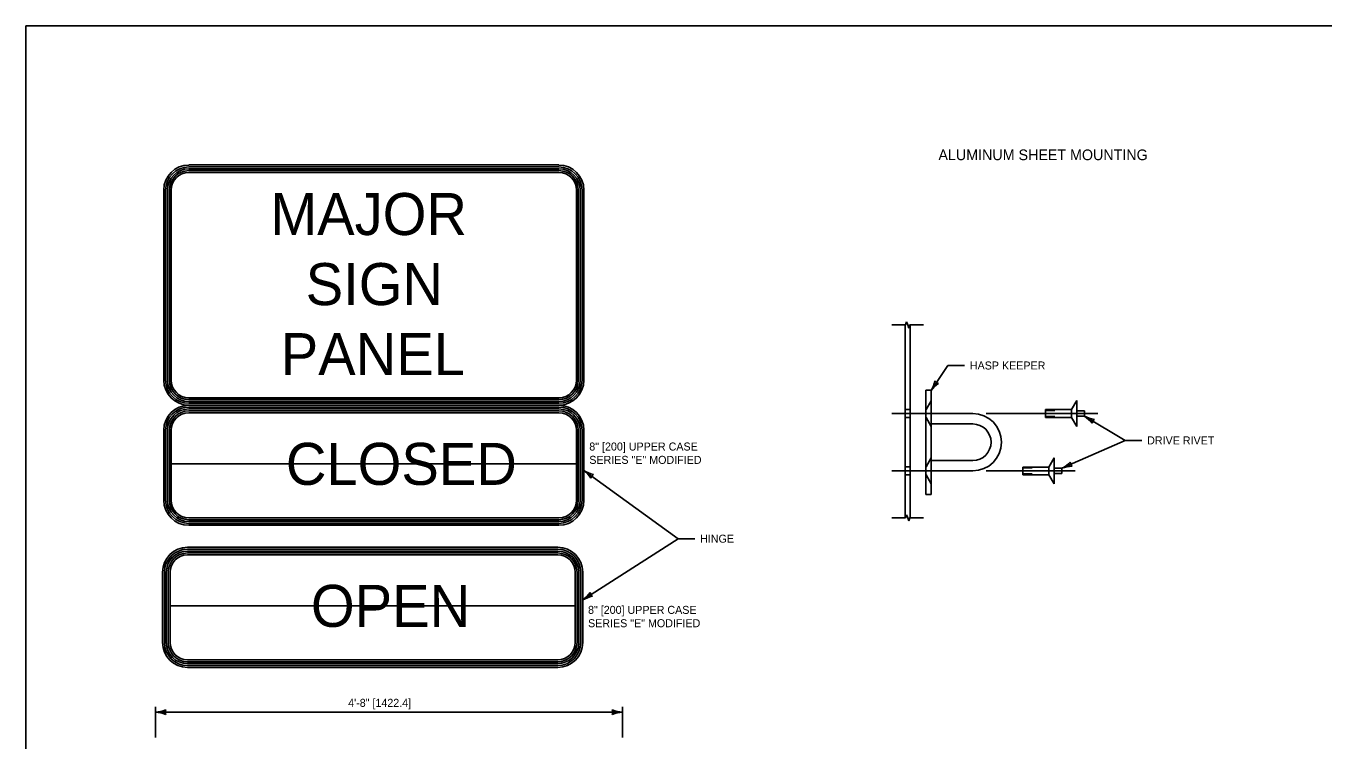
# Model space of a CAD drawing. Extents: x 49991.4 to 50021, y 49987.6 to 50011.4.
# Drawn here: x 49999.38 to 50009.11, y 49993.65 to 49999 of the extents above; entities that cross this region are included whole.
import ezdxf

# ---------------------------------------------------------------- set-up
doc = ezdxf.new("R2010")
doc.units = 0
for name, color, linetype in [('Level 1', 7, 'Continuous'), ('Level 2', 7, 'Continuous'), ('Level 3', 7, 'Continuous'), ('Level 4', 7, 'Continuous'), ('Level 5', 7, 'Continuous'), ('Level 6', 7, 'Continuous')]:
    doc.layers.add(name, color=color, linetype=linetype)

msp = doc.modelspace()

# ---------------------------------------------------------------- linework, layer by layer
at = {"layer": 'Level 1'}
for p, q in [((50003.3795, 49997.9572), (50000.6042, 49997.9572)), ((50003.3795, 49997.9431), (50000.6042, 49997.9431)), ((50003.3795, 49997.9291), (50000.6042, 49997.9291)), ((50003.3795, 49997.915), (50000.6042, 49997.915)), ((50003.3795, 49997.901), (50000.6042, 49997.901)), ((50000.4167, 49997.7697), (50000.4167, 49996.3447)), ((50000.4307, 49997.7697), (50000.4307, 49996.3447)), ((50000.4448, 49997.7697), (50000.4448, 49996.3447)), ((50000.4588, 49997.7697), (50000.4588, 49996.3447)), ((50000.4729, 49997.7697), (50000.4729, 49996.3447)), ((50003.5107, 49996.3447), (50003.5107, 49997.7697)), ((50003.5247, 49996.3447), (50003.5247, 49997.7697)), ((50003.5388, 49996.3447), (50003.5388, 49997.7697)), ((50003.5528, 49996.3447), (50003.5528, 49997.7697)), ((50003.567, 49996.3447), (50003.567, 49997.7697)), ((50005.9746, 49996.7584), (50005.9746, 49995.3132)), ((50006.0136, 49996.7584), (50006.0136, 49995.3132)), ((50000.6042, 49996.2135), (50003.3795, 49996.2135)), ((50000.6042, 49996.1993), (50003.3795, 49996.1993)), ((50000.6042, 49996.1853), (50003.3795, 49996.1853)), ((50006.1308, 49996.2703), (50006.1308, 49995.4891)), ((50006.1308, 49996.2703), (50006.1698, 49996.2703)), ((50006.1698, 49996.2703), (50006.1698, 49995.4891)), ((50007.2612, 49996.1919), (50007.2222, 49996.1237)), ((50007.2612, 49996.1919), (50007.2612, 49995.9967)), ((50000.6042, 49996.1712), (50003.3795, 49996.1712)), ((50000.6042, 49996.1572), (50003.3795, 49996.1572)), ((50003.3795, 49996.1431), (50000.6042, 49996.1431)), ((50003.3795, 49996.1291), (50000.6042, 49996.1291)), ((50003.3795, 49996.115), (50000.6042, 49996.115)), ((50003.3795, 49996.1009), (50000.6042, 49996.1009)), ((50006.1698, 49996.0944), (50006.4823, 49996.0944)), ((50007.0268, 49996.1237), (50007.2222, 49996.1237)), ((50007.0268, 49996.1237), (50007.0268, 49996.065)), ((50007.0268, 49996.117), (50007.0965, 49996.117)), ((50007.2222, 49996.1237), (50007.2222, 49996.065)), ((50007.2612, 49996.1139), (50007.3198, 49996.1139)), ((50007.3198, 49996.1139), (50007.3198, 49996.0748)), ((50006.1698, 49996.0163), (50006.4823, 49996.0163)), ((50007.0268, 49996.0732), (50007.0965, 49996.0732)), ((50007.0268, 49996.065), (50007.2222, 49996.065)), ((50007.2612, 49995.9967), (50007.2222, 49996.065)), ((50007.2612, 49996.0748), (50007.3198, 49996.0748)), ((50000.4167, 49995.9697), (50000.4167, 49995.4446)), ((50000.4307, 49995.9697), (50000.4307, 49995.4446)), ((50000.4448, 49995.9697), (50000.4448, 49995.4446)), ((50000.4588, 49995.9697), (50000.4588, 49995.4446)), ((50000.4729, 49995.9697), (50000.4729, 49995.4446)), ((50003.5107, 49995.4446), (50003.5107, 49995.9697)), ((50003.5247, 49995.4446), (50003.5247, 49995.9697)), ((50003.5388, 49995.4446), (50003.5388, 49995.9697)), ((50003.5528, 49995.4446), (50003.5528, 49995.9697)), ((50003.567, 49995.4446), (50003.567, 49995.9697)), ((50003.5107, 49995.7174), (50000.4729, 49995.7174)), ((50006.1698, 49995.7428), (50006.4823, 49995.7428)), ((50007.0915, 49995.7623), (50007.0525, 49995.6939)), ((50007.0915, 49995.7623), (50007.0915, 49995.5669)), ((50006.1698, 49995.6646), (50006.4823, 49995.6646)), ((50006.8571, 49995.6939), (50007.0525, 49995.6939)), ((50006.8571, 49995.6939), (50006.8571, 49995.6353)), ((50006.8571, 49995.6874), (50006.9267, 49995.6874)), ((50006.8571, 49995.6434), (50006.9267, 49995.6434)), ((50006.8571, 49995.6353), (50007.0525, 49995.6353)), ((50007.0525, 49995.6939), (50007.0525, 49995.6353)), ((50007.0915, 49995.5669), (50007.0525, 49995.6353)), ((50007.0915, 49995.6841), (50007.15, 49995.6841)), ((50007.0915, 49995.6451), (50007.1501, 49995.6451)), ((50007.15, 49995.6841), (50007.15, 49995.6452)), ((50006.1308, 49995.4891), (50006.1698, 49995.4891)), ((50000.6042, 49995.3132), (50003.3795, 49995.3132)), ((50000.6042, 49995.2991), (50003.3795, 49995.2991)), ((50000.6042, 49995.2851), (50003.3795, 49995.2851)), ((50000.6042, 49995.2709), (50003.3795, 49995.2709)), ((50000.6042, 49995.2569), (50003.3795, 49995.2569)), ((50000.5948, 49995.0921), (50003.3701, 49995.0921)), ((50003.3701, 49995.0781), (50000.5948, 49995.0781)), ((50003.3701, 49995.0639), (50000.5948, 49995.0639)), ((50003.3701, 49995.0499), (50000.5948, 49995.0499)), ((50003.3701, 49995.0358), (50000.5948, 49995.0358)), ((50000.4073, 49994.9046), (50000.4073, 49994.3796)), ((50000.4213, 49994.9046), (50000.4213, 49994.3796)), ((50000.4354, 49994.9046), (50000.4354, 49994.3796)), ((50000.4494, 49994.9046), (50000.4494, 49994.3796)), ((50000.4636, 49994.9046), (50000.4636, 49994.3796)), ((50003.5013, 49994.3796), (50003.5013, 49994.9046)), ((50003.5153, 49994.3796), (50003.5153, 49994.9046)), ((50003.5295, 49994.3796), (50003.5295, 49994.9046)), ((50003.5435, 49994.3796), (50003.5435, 49994.9046)), ((50003.5576, 49994.3796), (50003.5576, 49994.9046)), ((50000.4636, 49994.6532), (50003.5013, 49994.6532)), ((50000.5948, 49994.2483), (50003.3701, 49994.2483)), ((50000.5948, 49994.2343), (50003.3701, 49994.2343)), ((50000.5948, 49994.2202), (50003.3701, 49994.2202)), ((50000.5948, 49994.2062), (50003.3701, 49994.2062)), ((50000.5948, 49994.1921), (50003.3701, 49994.1921))]:
    msp.add_line(p, q, dxfattribs=at)
msp.add_lwpolyline([(49999.3835, 49998.9992), (50016.7501, 49998.9992), (50016.7501, 49987.7988), (49999.3835, 49987.7988)], close=True, dxfattribs=at)
for centre, radius, start, end in [((50000.6043, 49997.7695), 0.1875, 90, 180), ((50000.6043, 49997.7695), 0.1734, 90, 180), ((50003.3793, 49997.7695), 0.1875, 0, 90), ((50003.3793, 49997.7695), 0.1734, 0, 90), ((50000.6043, 49997.7695), 0.1594, 90, 180), ((50000.6043, 49997.7695), 0.1453, 90, 180), ((50000.6043, 49997.7695), 0.1313, 90, 180), ((50003.3793, 49997.7695), 0.1594, 0, 90), ((50003.3793, 49997.7695), 0.1453, 0, 90), ((50003.3793, 49997.7695), 0.1313, 0, 90), ((50000.6043, 49996.3445), 0.1875, 180, 270), ((50000.6043, 49996.3445), 0.1734, 180, 270), ((50000.6043, 49996.3445), 0.1594, 180, 270), ((50000.6043, 49996.3445), 0.1453, 180, 270), ((50000.6043, 49996.3445), 0.1313, 180, 270), ((50003.3793, 49996.3445), 0.1875, 270, 0), ((50003.3793, 49996.3445), 0.1734, 270, 0), ((50003.3793, 49996.3445), 0.1594, 270, 0), ((50003.3793, 49996.3445), 0.1453, 270, 0), ((50003.3793, 49996.3445), 0.1313, 270, 0), ((50000.6043, 49995.9695), 0.1875, 90, 180), ((50000.6043, 49995.9695), 0.1734, 90, 180), ((50000.6043, 49995.9695), 0.1594, 90, 180), ((50000.6043, 49995.9695), 0.1453, 90, 180), ((50000.6043, 49995.9695), 0.1313, 90, 180), ((50003.3793, 49995.9695), 0.1875, 0, 90), ((50003.3793, 49995.9695), 0.1734, 0, 90), ((50003.3793, 49995.9695), 0.1594, 0, 90), ((50003.3793, 49995.9695), 0.1453, 0, 90), ((50003.3793, 49995.9695), 0.1313, 0, 90), ((50006.4823, 49995.8795), 0.2149, 270, 90), ((50006.4823, 49995.8796), 0.1367, 270, 90), ((50000.6043, 49995.4445), 0.1875, 180, 270), ((50000.6043, 49995.4445), 0.1734, 180, 270), ((50000.6043, 49995.4445), 0.1594, 180, 270), ((50000.6043, 49995.4445), 0.1453, 180, 270), ((50000.6043, 49995.4445), 0.1313, 180, 270), ((50003.3793, 49995.4445), 0.1875, 270, 0), ((50003.3793, 49995.4445), 0.1734, 270, 0), ((50003.3793, 49995.4445), 0.1453, 270, 0), ((50003.3793, 49995.4445), 0.1594, 270, 0), ((50003.3793, 49995.4445), 0.1313, 270, 0), ((50000.5949, 49994.9046), 0.1875, 90, 180), ((50000.5949, 49994.9046), 0.1734, 90, 180), ((50000.5949, 49994.9046), 0.1594, 90, 180), ((50000.5949, 49994.9046), 0.1453, 90, 180), ((50000.5949, 49994.9046), 0.1313, 90, 180), ((50003.3699, 49994.9046), 0.1875, 0, 90), ((50003.3699, 49994.9046), 0.1734, 0, 90), ((50003.3699, 49994.9046), 0.1594, 0, 90), ((50003.3699, 49994.9046), 0.1453, 0, 90), ((50003.3699, 49994.9046), 0.1313, 0, 90), ((50000.5949, 49994.3796), 0.1875, 180, 270), ((50000.5949, 49994.3796), 0.1734, 180, 270), ((50000.5949, 49994.3796), 0.1594, 180, 270), ((50000.5949, 49994.3796), 0.1453, 180, 270), ((50000.5949, 49994.3796), 0.1313, 180, 270), ((50003.3699, 49994.3796), 0.1875, 270, 0), ((50003.3699, 49994.3796), 0.1734, 270, 0), ((50003.3699, 49994.3796), 0.1453, 270, 0), ((50003.3699, 49994.3796), 0.1594, 270, 0), ((50003.3699, 49994.3796), 0.1313, 270, 0)]:
    msp.add_arc(centre, radius, start, end, dxfattribs=at)
at = {"layer": 'Level 3'}
for p, q in [((50006.2951, 49996.4547), (50006.1698, 49996.2665)), ((50006.42, 49996.4547), (50006.2951, 49996.4547)), ((50007.3197, 49996.0748), (50007.6244, 49995.8933)), ((50007.6244, 49995.8933), (50007.15, 49995.6841)), ((50007.7493, 49995.8933), (50007.6244, 49995.8933)), ((50004.2728, 49995.1567), (50003.567, 49995.668)), ((50004.2728, 49995.1567), (50003.5576, 49994.6978)), ((50004.3977, 49995.1567), (50004.2728, 49995.1567)), ((50000.3555, 49993.8966), (50000.3555, 49993.6677)), ((50003.8556, 49993.8566), (50000.3555, 49993.8566)), ((50003.8556, 49993.8966), (50003.8556, 49993.6677))]:
    msp.add_line(p, q, dxfattribs=at)
for centre, radius, start, end in [((50005.9697, 49996.3859), 0.233, 329.17497, 348.42482), ((50006.3496, 49996.1358), 0.2223, 123.80367, 143.98718), ((50006.2409, 49996.3732), 0.0548, 218.48648, 254.20884), ((50007.1981, 49995.8886), 0.2223, 36.67279, 56.8563), ((50007.4289, 49996.2806), 0.233, 242.04409, 261.29394), ((50007.4299, 49996.0092), 0.0548, 131.3556, 167.07796), ((50007.0456, 49995.8924), 0.233, 296.62861, 315.87846), ((50007.2313, 49995.4772), 0.2223, 91.25731, 111.44082), ((50007.2673, 49995.7358), 0.0548, 185.94012, 221.66248), ((50003.4293, 49995.4935), 0.2223, 31.53435, 51.71786), ((50003.6942, 49995.8632), 0.233, 236.90565, 256.1555), ((50003.6708, 49995.5928), 0.0548, 126.21716, 161.93952), ((50003.4223, 49994.8875), 0.233, 305.51327, 324.76312), ((50003.6655, 49994.767), 0.0548, 194.82478, 230.54714), ((50003.6699, 49994.5059), 0.2223, 100.14197, 120.32548), ((50000.344, 49994.0893), 0.233, 272.82731, 292.07716), ((50000.3463, 49993.6345), 0.2223, 67.45601, 87.63952), ((50000.4837, 49993.8566), 0.0548, 162.13882, 197.86118), ((50003.8648, 49994.0787), 0.2223, 247.45601, 267.63952), ((50003.7274, 49993.8566), 0.0548, 342.13882, 17.86118), ((50003.8671, 49993.6239), 0.233, 92.82731, 112.07716)]:
    msp.add_arc(centre, radius, start, end, dxfattribs=at)
at = {"layer": 'Level 4'}
for p, q in [((50006.1698, 49996.191), (50006.1313, 49996.1239)), ((50005.9746, 49996.1237), (50006.0136, 49996.1237)), ((50005.9746, 49996.065), (50006.0136, 49996.065)), ((50006.1698, 49995.9981), (50006.1313, 49996.0653)), ((50006.1708, 49995.7625), (50006.1317, 49995.6943)), ((50005.9746, 49995.694), (50006.0136, 49995.694)), ((50005.9746, 49995.6354), (50006.0136, 49995.6354)), ((50006.1708, 49995.5673), (50006.1317, 49995.6356))]:
    msp.add_line(p, q, dxfattribs=at)
at = {"layer": 'Level 5'}
for p, q in [((50005.8746, 49996.0944), (50006.1698, 49996.0944)), ((50006.5823, 49996.0943), (50007.4198, 49996.0943)), ((50005.8746, 49995.6648), (50006.1698, 49995.6648)), ((50006.5825, 49995.6646), (50007.2501, 49995.6646))]:
    msp.add_line(p, q, dxfattribs=at)
at = {"layer": 'Level 6'}
for p, q in [((50005.986, 49996.7812), (50005.9779, 49996.7584)), ((50005.986, 49996.7812), (50005.9941, 49996.7584)), ((50005.9779, 49996.7584), (50005.8746, 49996.7584)), ((50005.9941, 49996.7584), (50006.0022, 49996.7356)), ((50006.0103, 49996.7584), (50006.0022, 49996.7356)), ((50006.1136, 49996.7584), (50006.0103, 49996.7584)), ((50005.9779, 49995.3132), (50005.8746, 49995.3132)), ((50005.986, 49995.336), (50005.9779, 49995.3132)), ((50005.986, 49995.336), (50005.9941, 49995.3132)), ((50005.9941, 49995.3132), (50006.0022, 49995.2904)), ((50006.0103, 49995.3132), (50006.0022, 49995.2904)), ((50006.1136, 49995.3132), (50006.0103, 49995.3132))]:
    msp.add_line(p, q, dxfattribs=at)

# ---------------------------------------------------------------- texts
at = {"layer": 'Level 1'}
for s, p in [('MAJOR', (50001.2158, 49997.4322)), ('SIGN', (50001.4808, 49996.9072)), ('PANEL', (50001.2937, 49996.3822)), ('CLOSED', (50001.3319, 49995.5599)), ('OPEN', (50001.5201, 49994.4957))]:
    msp.add_text(s, height=0.315, dxfattribs=at).set_placement(p)
at = {"layer": 'Level 2'}
for s, height, p in [('ALUMINUM SHEET MOUNTING', 0.08, (50006.2246, 49997.9934)), ('HASP KEEPER', 0.06, (50006.46, 49996.4247)), ('DRIVE RIVET', 0.06, (50007.7893, 49995.8633)), ('8" [200] UPPER CASE', 0.06, (50003.607, 49995.8174)), ('SERIES "E" MODIFIED', 0.06, (50003.607, 49995.7174)), ('HINGE', 0.06, (50004.4377, 49995.1267)), ('8" [200] UPPER CASE', 0.06, (50003.5976, 49994.5932)), ('SERIES "E" MODIFIED', 0.06, (50003.5976, 49994.4932)), ('4\'-8" [1422.4]', 0.06, (50001.7993, 49993.8966))]:
    msp.add_text(s, height=height, dxfattribs=at).set_placement(p)

doc.saveas('drawing.dxf')
